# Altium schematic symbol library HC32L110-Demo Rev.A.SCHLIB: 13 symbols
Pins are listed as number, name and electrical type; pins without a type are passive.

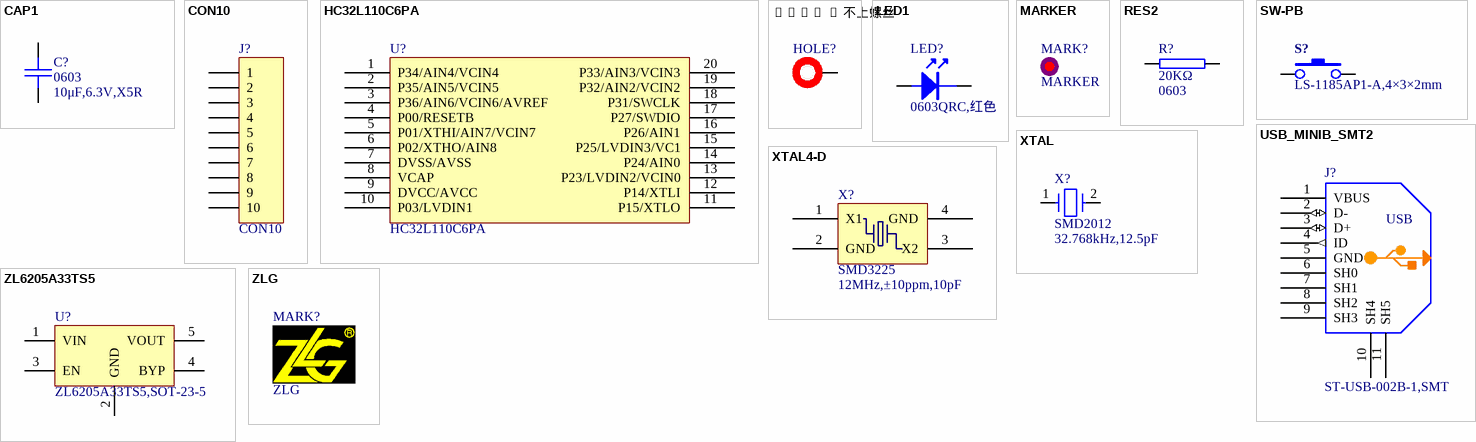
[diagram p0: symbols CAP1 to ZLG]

## CAP1
designator C?, comment 封装: 0603  型号: 10μF,6.3V,X5R  (hidden comment: 10μF,6.3V)
10μF,6.3V,X5R,GRM188R60J106M****,0603,Murata,RoHS; 物料代码: 1.02.01.0065; 名称: 电容; 贴片和直插: SMT; 器件优选方案: 正常状态，可以选用
footprint 0603C
pins: 1, 2
2 alternate drawings of the same symbol

## CON10
designator J?
Connector
footprint SIP-10-2.54
pins: 1, 2, 3, 4, 5, 6, 7, 8, 9, 10
2 alternate drawings of the same symbol

## HC32L110C6PA
designator U?
footprint TSSOP20 (Shrink Small Outline; 20 Leads; Body Width 4.4 mm; Pitch 0.65 mm)
pins: 1 P34/AIN4/VCIN4, 2 P35/AIN5/VCIN5, 3 P36/AIN6/VCIN6/AVREF, 4 P00/RESETB, 5 P01/XTHI/AIN7/VCIN7, 6 P02/XTHO/AIN8, 7 DVSS/AVSS, 8 VCAP, 9 DVCC/AVCC, 10 P03/LVDIN1, 11 P15/XTLO, 12 P14/XTLI, 13 P23/LVDIN2/VCIN0, 14 P24/AIN0, 15 P25/LVDIN3/VC1, 16 P26/AIN1, 17 P27/SWDIO, 18 P31/SWCLK, 19 P32/AIN2/VCIN2, 20 P33/AIN3/VCIN3

## HOLE - 不上螺丝
designator HOLE?  (no BOM)
footprint HOLE-2.2
footprint HOLE-3.2
pins: 1

## LED1
designator LED?, comment 0603QRC,红色
0603QRC,红色,0603,创光,RoHS; 物料代码: 1.04.05.0008; 名称: 发光二极管; 封装: 0603; 设备封装名称: LED0603-RED; 贴片和直插: SMT; 器件优选方案: 正常状态，可以选用
footprint LED-0603
pins: 1, 2
2 alternate drawings of the same symbol

## MARKER
designator MARK?
footprint MARKER-C-1.0M
footprint MARKER-S
pins: 0

## RES2
designator R?, comment 封装: 0603  (hidden comment: 20KΩ)
20KΩ,0603,*,RoHS; 物料代码: 1.01.01.0056; 名称: 电阻; 设备封装名称: R0603_20K; 厂商: Ralec; 贴片和直插: SMT; 器件优选方案: 正常状态，可以选用
footprint 0603R
pins: 1, 2
2 alternate drawings of the same symbol

## SW-PB
designator S?, comment LS-1185AP1-A,4×3×2mm
LS-1185AP1-A,4×3×2mm,SMD,4×3×2mm,CKC,RoHS; 物料代码: 1.09.01.0017; 名称: 轻触开关; 贴片和直插: SMT; PCB备注: 161024 HCJ; 器件优选方案: 正常状态，可以选用
footprint KEY-400X300X200P
pins: 1, 2
2 alternate drawings of the same symbol

## USB_MINIB_SMT2
designator J?, comment ST-USB-002B-1,SMT
ST-USB-002B-1,SMT,SUNGTECH,MicroUSB-A; 物料代码: 20.02.00033; 名称: 连接器; PCB备注: 190710lmd; 器件优选方案: 通用物料
footprint MICROUSB-ST-USB-002B-1
pins: 1 VBUS, 2 D- (io), 3 D+ (io), 4 ID (out), 5 GND (power), 6 SH0, 7 SH1, 8 SH2, 9 SH3, 10 SH4, 11 SH5

## XTAL
designator X?, comment 封装: SMD2012  型号: 32.768kHz,12.5pF  (hidden comment: SC-20S,32.768kHz)
SC-20S,32.768kHz,12.5pF,±20ppm,SMD2012,SII; 物料代码: 1.07.01.0071; 名称: 晶体(临时); 贴片和直插: SMT; PCB备注: 180227ZW; 器件优选方案: 临时/偏门物料/不主推物料，谨慎选用
footprint XTAL205X120X60-2N
pins: 1, 2

## XTAL4-D
designator X?, comment 封装: SMD3225  型号: 12MHz,±10ppm,10pF  (hidden comment: JYD3A1C7G6-10-12.000,12.0000MHz)
JYD3A1C7G6-10-12.000,12.0000MHz,±10ppm,10pF,-40~85℃,±10ppm,SMD3225,*,JYEG,RoHS; 物料代码: 1.07.01.0032; 名称: 晶体; 贴片和直插: SMT; PCB备注: 151229lmd171128ZW; 器件优选方案: 正常状态，可以选用
footprint OSCCC250X320X80-4N
pins: 1 X1, 2 GND, 3 X2, 4 GND

## ZL6205A33TS5
designator U?, comment ZL6205A33TS5,SOT-23-5
ZL6205A33TS5,SOT-23-5,ZLG; 物料代码: 08.09.03069; 名称: 集成电路; 贴片和直插: SMT; PCB备注: 190806hcj; 器件优选方案: 待导入物料
footprint SOT-23-5
pins: 1 VIN, 2 GND, 3 EN, 4 BYP, 5 VOUT

## ZLG
designator MARK?  (no BOM)
footprint ZLG0.7 (Footprint not found)
footprint ZLG1.0
footprint ZLG1.5
footprint ZLG2.0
